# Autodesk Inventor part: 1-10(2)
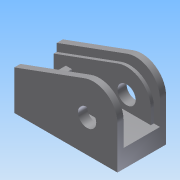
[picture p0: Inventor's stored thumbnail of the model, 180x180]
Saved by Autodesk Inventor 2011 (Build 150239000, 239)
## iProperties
Created: 2014-02
Part Number: 1-10(2)
Document SubType Name: Modeling
Designer: Administrator
Density: 1 g/cm^3
Author: Administrator
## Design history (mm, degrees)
sketch "草图1"
  geometry: L1 (-15, 8)-(15, 8); L2 (15, 8)-(15, -8); L3 (15, -8)-(-15, -8); L4 (-15, -8)-(-15, 8); 3 further points
  constraints: 8 end point, 2 midpoint, 2 parallel, 1 horizontal, 1 horizontal alignment, 1 perpendicular, 1 vertical alignment
extrude "拉伸1" new body sketch "草图1" distance "d0" = 6; taper "d1" = 0 deg
sketch "草图2"
  geometry: L1 (30, 6)-(0, 6) reference; L2 (0, 0)-(0, 6) reference; L3 (30, 0)-(0, 0) reference; L4 (30, 0)-(30, 6) reference; L5 (30, 0)-(30, 14); L6 (30, 0)-(-4, 0); L7 (-4, 0)-(-4, 13); L8 (-4, 13)-(19.25, 21.512); A1 r 8 centre (22, 14) between (30, 14) and (19.25, 21.512); 1 further point
  constraints: 8 end point, 2 point on circle, 2 point on line, 1 centre point, 1 tangent
  dimensions: "d2" = 14 distance of L3.start L5.end; "d3" = 34 distance of L3.start L6.end; "d6" = 13 distance of L6.end L7.end; "d20" = 8 radius of A1
extrude "拉伸2" join sketch "草图2" distance "d7" = 2; taper "d8" = 0 deg
sketch "草图3"
  geometry: L1 (0, 0)-(0, -6) reference; L2 (-4, 0)-(0, 0) reference; L3 (-4, -13)-(-4, 0) reference; L4 (19.25, -21.512)-(-4, -13) reference; L5 (0, -6)-(30, -6) reference; L6 (-4, 0)-(-4, -10.437); L7 (30, -6)-(30, -14) reference; L8 (27.986, -6)-(27.986, -10.935); L9 (17.239, -18.213)-(-4, -10.437); A1 r 8 centre (19.99, -10.701) between (17.239, -18.213) and (27.986, -10.935); 1 further point
  constraints: 6 end point, 2 parallel, 2 point on circle, 2 point on line, 1 centre point, 1 tangent
  dimensions: "d21" = 8 radius of A1
extrude "拉伸3" join sketch "草图3" distance "d9" = 1; taper "d10" = 0 deg
mirror "镜像1"
sketch "草图4"
  geometry: L1 (-15, -5)-(12.986, -5) reference; L2 (-15, 5)-(-13, 5); L3 (-13, 5)-(-13, -5); L4 (-13, -5)-(-15, -5); L5 (-15, -5)-(-15, 5); 1 further point
  constraints: 8 end point, 2 parallel, 1 horizontal, 1 perpendicular, 1 point on line
extrude "拉伸4" join sketch "草图4" distance "d11" = 3; taper "d12" = 0 deg
sketch "草图5"
  geometry: L1 (-12.986, 5)-(13, 5) reference; L2 (13, -5)-(-12.986, -5) reference; L3 (5, -2)-(-5, -2); L4 (5, 2)-(-5, 2); A1 r 2 centre (5, 0) between (5, -2) and (5, 2); A2 r 2 centre (-5, 0) between (-5, 2) and (-5, -2); 1 further point
  constraints: 4 end point, 4 point on circle, 2 centre point, 2 tangent
  dimensions: "d13" = 4 diameter of A1; "d14" = 4 diameter of A2
extrude "拉伸5" cut sketch "草图5" stored distance "d15" = 3; taper "d16" = 0 deg
sketch "草图6"
  geometry: C1 r 3 at (23.99, 10.701); A1 r 8 centre (23.99, 10.701) between (31.986, 10.935) and (21.239, 18.213) reference; 1 further point
  constraints: 1 centre point, 1 coincident
  dimensions: "d17" = 6 diameter of C1
extrude "拉伸6" cut sketch "草图6" stored distance "d18" = 3; taper "d19" = 0 deg
node "实体1"
